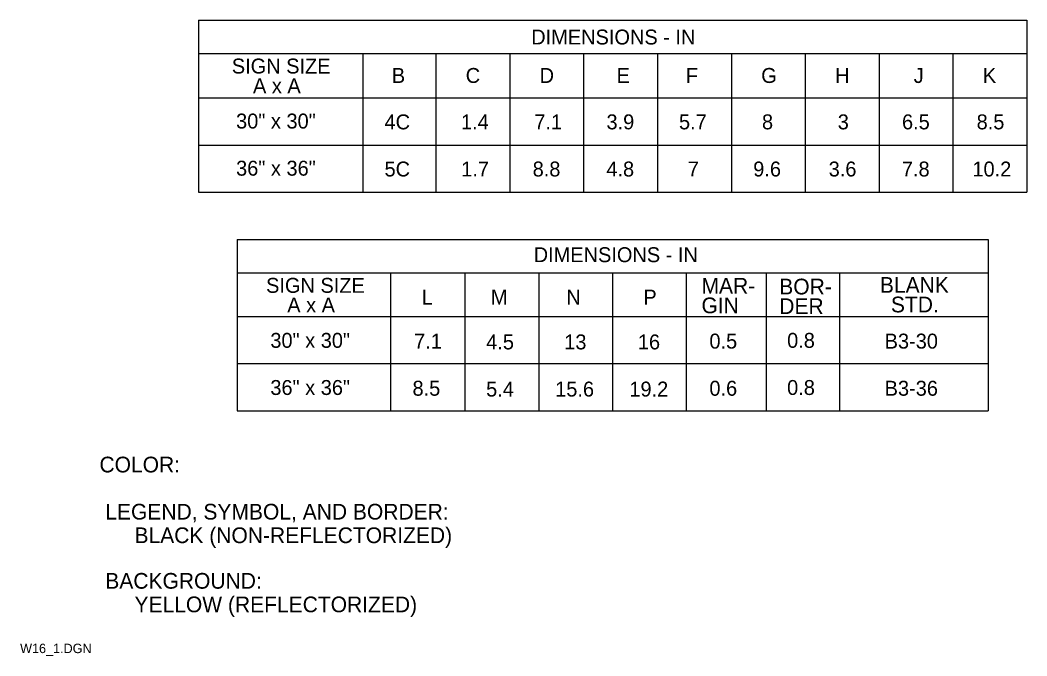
# Model space of a CAD drawing. Extents: x 0.012 to 0.188, y 0.004 to 0.259.
# Drawn here: x 0.0124 to 0.1725, y 0.0039 to 0.1051 of the extents above; entities that cross this region are included whole.
import ezdxf

# ---------------------------------------------------------------- set-up
doc = ezdxf.new("R2010")
doc.units = 0
doc.layers.add('1', color=7, linetype='Continuous')
doc.layers.add('3', color=7, linetype='Continuous')

msp = doc.modelspace()

# ---------------------------------------------------------------- linework, layer by layer
at = {"layer": '3'}
for p, q in [((0.04075, 0.10509), (0.1725, 0.10509)), ((0.04075, 0.10509), (0.04075, 0.07771)), ((0.1725, 0.10509), (0.1725, 0.07771)), ((0.1725, 0.09971), (0.04075, 0.09971)), ((0.06689, 0.09976), (0.06689, 0.07771)), ((0.0785, 0.09971), (0.0785, 0.07771)), ((0.09025, 0.09971), (0.09025, 0.07771)), ((0.102, 0.09971), (0.102, 0.07771)), ((0.11375, 0.09971), (0.11375, 0.07771)), ((0.1255, 0.09971), (0.1255, 0.07771)), ((0.13725, 0.09971), (0.13725, 0.07771)), ((0.149, 0.09971), (0.149, 0.07771)), ((0.16075, 0.09971), (0.16075, 0.07771)), ((0.04075, 0.09271), (0.1725, 0.09271)), ((0.04075, 0.08521), (0.1725, 0.08521)), ((0.04075, 0.07771), (0.1725, 0.07771)), ((0.04688, 0.0702), (0.16637, 0.0702)), ((0.04688, 0.0702), (0.04688, 0.04295)), ((0.16637, 0.0702), (0.16637, 0.04295)), ((0.16637, 0.06483), (0.04688, 0.06483)), ((0.0713, 0.06483), (0.0713, 0.04295)), ((0.08313, 0.06483), (0.08313, 0.04295)), ((0.09488, 0.06483), (0.09488, 0.04295)), ((0.10662, 0.06483), (0.10662, 0.04295)), ((0.1183, 0.06483), (0.1183, 0.04295)), ((0.13106, 0.06483), (0.13106, 0.04295)), ((0.14271, 0.06483), (0.14271, 0.04295)), ((0.04688, 0.05795), (0.16637, 0.05795)), ((0.04688, 0.05045), (0.16637, 0.05045)), ((0.04688, 0.04295), (0.16637, 0.04295))]:
    msp.add_line(p, q, dxfattribs=at)

# ---------------------------------------------------------------- texts
at = {"layer": '1'}
for s, height, p in [('COLOR:', 0.0025, (0.025, 0.03313)), (' LEGEND, SYMBOL, AND BORDER:', 0.0024998, (0.025, 0.02563)), ('      BLACK (NON-REFLECTORIZED)', 0.0024998, (0.025, 0.02188)), (' BACKGROUND:', 0.0024998, (0.025, 0.01463)), ('      YELLOW (REFLECTORIZED)', 0.0024998, (0.025, 0.01088)), ('W16_1.DGN', 0.0015, (0.01238, 0.00438))]:
    msp.add_text(s, height=height, dxfattribs=at).set_placement(p)
at = {"layer": '3'}
for s, height, p in [('DIMENSIONS - IN', 0.0023752, (0.09367, 0.10121)), ('SIGN SIZE', 0.002375, (0.04605, 0.09659)), ('B', 0.00238, (0.0715, 0.09509)), ('C', 0.00238, (0.08325, 0.09509)), ('D', 0.00238, (0.095, 0.09509)), ('E', 0.00238, (0.10725, 0.09509)), ('F', 0.00238, (0.11825, 0.09509)), ('G', 0.00238, (0.13025, 0.09509)), ('H', 0.00238, (0.142, 0.09509)), ('J', 0.00238, (0.1545, 0.09509)), ('K', 0.00238, (0.1655, 0.09509)), ('A x A', 0.002375, (0.04942, 0.09346)), ('30" x 30"', 0.002375, (0.04673, 0.08784)), ('4C', 0.002375, (0.07034, 0.08771)), ('1.4', 0.002375, (0.0825, 0.08771)), ('7.1', 0.002375, (0.09416, 0.08771)), ('3.9', 0.002375, (0.10564, 0.08771)), ('5.7', 0.002375, (0.11717, 0.08771)), ('8', 0.00238, (0.13037, 0.08771)), ('3', 0.00238, (0.14242, 0.08771)), ('6.5', 0.002375, (0.15264, 0.08771)), ('8.5', 0.002375, (0.16451, 0.08771)), ('36" x 36"', 0.002375, (0.04673, 0.08034)), ('5C', 0.002375, (0.07034, 0.08021)), ('1.7', 0.002375, (0.08254, 0.08021)), ('8.8', 0.002375, (0.0939, 0.08021)), ('4.8', 0.002375, (0.10562, 0.08021)), ('7', 0.00238, (0.11857, 0.08021)), ('9.6', 0.002375, (0.12898, 0.08021)), ('3.6', 0.002375, (0.14098, 0.08021)), ('7.8', 0.002375, (0.15262, 0.08021)), ('10.2', 0.002375, (0.16384, 0.08021)), ('DIMENSIONS - IN', 0.0023752, (0.09406, 0.06658)), ('SIGN SIZE', 0.002375, (0.0515, 0.0617)), ('MAR-', 0.0025, (0.12075, 0.06158)), ('BLANK', 0.0025, (0.14913, 0.06171)), ('BOR-', 0.0025, (0.13312, 0.06145)), ('A x A', 0.002375, (0.05487, 0.05858)), ('L', 0.00238, (0.07625, 0.05983)), ('M', 0.00238, (0.08725, 0.05983)), ('N', 0.00238, (0.09925, 0.05983)), ('P', 0.00238, (0.1115, 0.05983)), ('GIN', 0.0025, (0.12075, 0.05845)), ('STD.', 0.0025, (0.15088, 0.05859)), ('DER', 0.0025, (0.13312, 0.05833)), ('30" x 30"', 0.002375, (0.05218, 0.05295)), ('7.1', 0.002375, (0.07504, 0.05283)), ('4.5', 0.002375, (0.08651, 0.0527)), ('13', 0.002375, (0.09892, 0.0527)), ('16', 0.002375, (0.11063, 0.0527)), ('0.5', 0.002375, (0.12201, 0.05283)), ('0.8', 0.002375, (0.13437, 0.05295)), ('B3-30', 0.002375, (0.14988, 0.05283)), ('36" x 36"', 0.002375, (0.05218, 0.04545)), ('8.5', 0.002375, (0.07479, 0.04533)), ('5.4', 0.002375, (0.0865, 0.0452)), ('15.6', 0.002375, (0.09748, 0.0452)), ('19.2', 0.002375, (0.10928, 0.0452)), ('0.6', 0.002375, (0.12201, 0.04533)), ('0.8', 0.002375, (0.13437, 0.04545)), ('B3-36', 0.002375, (0.14988, 0.04533))]:
    msp.add_text(s, height=height, dxfattribs=at).set_placement(p)

doc.saveas('drawing.dxf')
